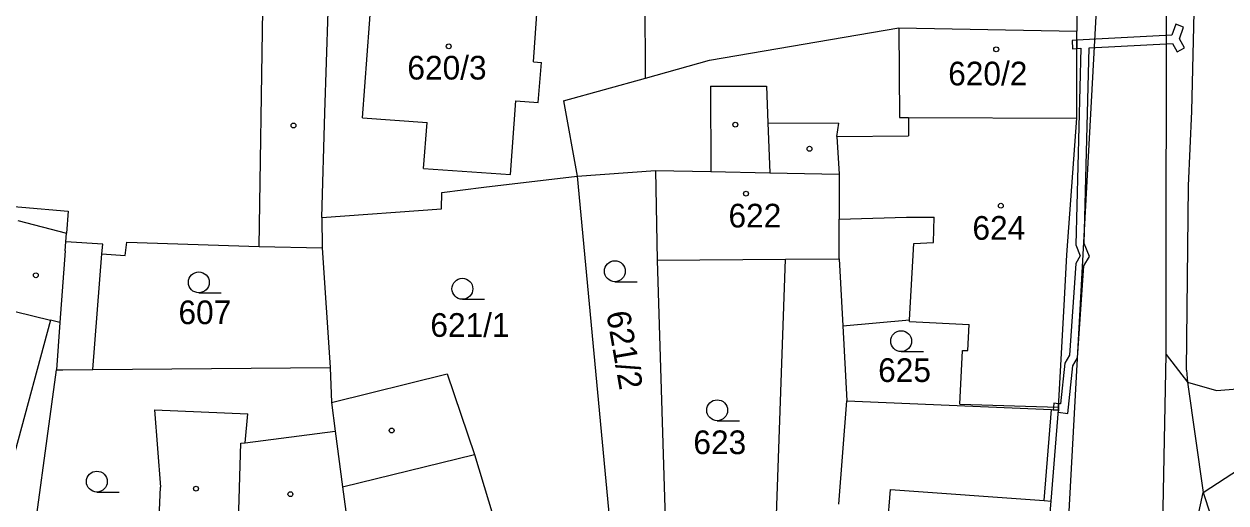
# Model space of a CAD drawing. Extents: x -785744 to -782822, y -1067550 to -1063910.
# Drawn here: x -783562.5 to -783476.2, y -1065679 to -1065644.6 of the extents above; entities that cross this region are included whole.
import ezdxf

# ---------------------------------------------------------------- set-up
doc = ezdxf.new("R2010")
doc.units = 0
for name, color, linetype in [('Hranice parcel', 7, 'Continuous'), ('Parcelní čísla', 7, 'Continuous'), ('Vnitřní kresba', 7, 'Continuous'), ('Věcná břemena k části', 7, 'Continuous'), ('Značky budov', 7, 'Continuous'), ('Značky kultur', 7, 'Continuous')]:
    doc.layers.add(name, color=color, linetype=linetype)

msp = doc.modelspace()

# ---------------------------------------------------------------- linework, layer by layer
at = {"layer": 'Hranice parcel'}
for p, q in [((-783517.88, -1065648.46), (-783517.92, -1065640.59)), ((-783517.88, -1065648.46), (-783513.29, -1065647.19)), ((-783523.78, -1065650.1), (-783517.88, -1065648.46)), ((-783559.36, -1065658.02), (-783559.47, -1065659.6)), ((-783562.96, -1065658.68), (-783559.47, -1065659.6)), ((-783560.63, -1065665.84), (-783563.19, -1065675.33)), ((-783559.94, -1065666.01), (-783560.63, -1065665.84))]:
    msp.add_line(p, q, dxfattribs=at)
for points in [[(-783486.9, -1065640.93), (-783486.91, -1065645.09)], [(-783478.66, -1065650.84), (-783478.44, -1065641.69)], [(-783538.22, -1065651.31), (-783537.54, -1065642.3)], [(-783540.91, -1065650.97), (-783540.69, -1065643.68)], [(-783525.94, -1065647.3), (-783525.64, -1065643.19)], [(-783513.29, -1065647.19), (-783499.7, -1065644.85)], [(-783499.7, -1065644.85), (-783486.91, -1065645.09)], [(-783486.92, -1065651.35), (-783486.91, -1065645.09)], [(-783525.94, -1065647.3), (-783525.37, -1065647.34)], [(-783525.59, -1065650.23), (-783525.37, -1065647.34)], [(-783527.59, -1065655.39), (-783527.19, -1065650.11)], [(-783527.19, -1065650.11), (-783525.59, -1065650.23)], [(-783523.78, -1065650.1), (-783522.79, -1065655.51)], [(-783541.14, -1065658.48), (-783540.91, -1065650.97)], [(-783538.22, -1065651.31), (-783533.58, -1065651.65)], [(-783533.83, -1065654.96), (-783533.58, -1065651.65)], [(-783499, -1065651.29), (-783486.92, -1065651.35)], [(-783499, -1065651.29), (-783498.99, -1065652.6)], [(-783487.62, -1065661.15), (-783486.92, -1065651.35)], [(-783478.89, -1065656.21), (-783478.66, -1065650.84)], [(-783504.15, -1065652.65), (-783498.99, -1065652.6)], [(-783504.15, -1065652.65), (-783503.99, -1065655.37)], [(-783533.83, -1065654.96), (-783527.59, -1065655.39)], [(-783522.79, -1065655.51), (-783517.17, -1065655.09)], [(-783517.17, -1065655.09), (-783517.06, -1065661.54)], [(-783517.17, -1065655.09), (-783513.19, -1065655.17)], [(-783529.51, -1065656.29), (-783522.79, -1065655.51)], [(-783522.79, -1065655.51), (-783520.15, -1065683.77)], [(-783513.19, -1065655.17), (-783508.95, -1065655.26)], [(-783508.95, -1065655.26), (-783503.99, -1065655.37)], [(-783503.99, -1065655.37), (-783503.98, -1065658.59)], [(-783532.55, -1065657.85), (-783532.52, -1065656.69)], [(-783532.52, -1065656.69), (-783529.51, -1065656.29)], [(-783479.03, -1065669.43), (-783478.89, -1065656.21)], [(-783566.02, -1065657.44), (-783559.36, -1065658.02)], [(-783541.14, -1065658.48), (-783532.55, -1065657.85)], [(-783541.14, -1065658.48), (-783541.1, -1065660.66)], [(-783503.98, -1065661.45), (-783503.98, -1065658.59)], [(-783559.56, -1065660.87), (-783559.51, -1065660.21)], [(-783559.51, -1065660.21), (-783559.47, -1065659.6)], [(-783555.25, -1065661.19), (-783555.14, -1065660.24)], [(-783555.14, -1065660.24), (-783545.64, -1065660.56)], [(-783559.56, -1065660.87), (-783559.94, -1065666.01)], [(-783557.59, -1065669.38), (-783556.93, -1065661.07)], [(-783556.93, -1065661.07), (-783555.25, -1065661.19)], [(-783545.64, -1065660.56), (-783541.1, -1065660.66)], [(-783541.1, -1065660.66), (-783540.54, -1065669.25)], [(-783487.82, -1065664.79), (-783487.62, -1065661.15)], [(-783517.06, -1065661.54), (-783507.83, -1065661.47)], [(-783517.06, -1065661.54), (-783516.43, -1065681.67)], [(-783508.51, -1065680.51), (-783507.83, -1065661.47)], [(-783503.98, -1065661.45), (-783503.72, -1065666.25)], [(-783488.23, -1065672.09), (-783487.82, -1065664.79)], [(-783559.94, -1065666.01), (-783560.19, -1065669.41)], [(-783503.72, -1065666.25), (-783498.94, -1065665.81)], [(-783503.72, -1065666.25), (-783503.43, -1065671.64)], [(-783498.94, -1065665.95), (-783498.94, -1065665.81)], [(-783498.94, -1065665.95), (-783494.64, -1065666.15)], [(-783494.73, -1065668.03), (-783494.64, -1065666.15)], [(-783495.32, -1065671.88), (-783495.13, -1065668.01)], [(-783495.13, -1065668.01), (-783494.73, -1065668.03)], [(-783476.88, -1065670.89), (-783441.51, -1065668.06)], [(-783562.28, -1065684.72), (-783560.19, -1065669.41)], [(-783560.19, -1065669.41), (-783559.74, -1065669.4)], [(-783559.74, -1065669.4), (-783557.59, -1065669.38)], [(-783557.59, -1065669.38), (-783540.54, -1065669.25)], [(-783540.54, -1065669.25), (-783540.44, -1065671.76)], [(-783540.44, -1065671.76), (-783532.13, -1065669.7)], [(-783532.13, -1065669.7), (-783530.18, -1065675.48)], [(-783479.03, -1065669.43), (-783478.96, -1065670.3)], [(-783478.96, -1065670.3), (-783477.83, -1065678.21)], [(-783478.96, -1065670.3), (-783476.88, -1065670.89)], [(-783553.15, -1065672.28), (-783552.72, -1065677.82)], [(-783553.15, -1065672.28), (-783546.46, -1065672.57)], [(-783540.44, -1065671.76), (-783540.18, -1065673.82)], [(-783504, -1065679.05), (-783503.43, -1065671.64)], [(-783503.43, -1065671.64), (-783488.73, -1065672.26)], [(-783495.32, -1065671.88), (-783488.23, -1065672.09)], [(-783488.76, -1065678.83), (-783488.24, -1065672.29)], [(-783488.73, -1065672.26), (-783488.24, -1065672.29)], [(-783488.24, -1065672.29), (-783488.23, -1065672.09)], [(-783546.64, -1065674.65), (-783546.46, -1065672.57)], [(-783546.64, -1065674.65), (-783540.18, -1065673.82)], [(-783540.18, -1065673.82), (-783539.65, -1065677.8)], [(-783530.18, -1065675.48), (-783528.46, -1065681.12)], [(-783552.92, -1065682.22), (-783552.72, -1065677.82)], [(-783539.65, -1065677.8), (-783538.64, -1065685.26)], [(-783477.83, -1065678.21), (-783476.79, -1065681.42)], [(-783489.53, -1065687.87), (-783488.76, -1065678.83)]]:
    msp.add_lwpolyline(points, dxfattribs=at)
at = {"layer": 'Vnitřní kresba'}
msp.add_line((-783564.63, -1065664.86), (-783560.63, -1065665.84), dxfattribs=at)
for points in [[(-783480.49, -1065668.31), (-783480.48, -1065638.77)], [(-783487.87, -1065687.01), (-783485.3, -1065640.06)], [(-783545.64, -1065660.56), (-783545.36, -1065643.57)], [(-783499.7, -1065644.85), (-783499.64, -1065651.29)], [(-783513.21, -1065649.04), (-783513.19, -1065655.17)], [(-783513.21, -1065649.04), (-783509.21, -1065649.05)], [(-783509.21, -1065649.05), (-783509.1, -1065651.69)], [(-783499.64, -1065651.29), (-783499, -1065651.29)], [(-783509.1, -1065651.69), (-783508.95, -1065655.26)], [(-783509.1, -1065651.69), (-783504, -1065651.71)], [(-783504.15, -1065652.65), (-783504, -1065651.71)], [(-783503.98, -1065658.59), (-783499.14, -1065658.45)], [(-783499.14, -1065658.45), (-783497.16, -1065658.44)], [(-783497.2, -1065660.26), (-783497.16, -1065658.44)], [(-783556.87, -1065660.38), (-783559.51, -1065660.21)], [(-783498.63, -1065660.34), (-783497.2, -1065660.26)], [(-783556.93, -1065661.07), (-783556.87, -1065660.38)], [(-783498.94, -1065665.81), (-783498.63, -1065660.34)], [(-783507.83, -1065661.47), (-783503.98, -1065661.45)], [(-783480.78, -1065683.02), (-783480.49, -1065668.31)], [(-783480.49, -1065668.31), (-783478.96, -1065670.3)], [(-783489.25, -1065678.79), (-783488.73, -1065672.26)], [(-783547.29, -1065685.92), (-783546.94, -1065674.68)], [(-783546.94, -1065674.68), (-783546.64, -1065674.65)], [(-783539.65, -1065677.8), (-783530.18, -1065675.48)], [(-783477.83, -1065678.21), (-783474.2, -1065675.85)], [(-783500.73, -1065683.36), (-783500.3, -1065678)], [(-783500.3, -1065678), (-783489.25, -1065678.79)], [(-783478.68, -1065682.09), (-783477.83, -1065678.21)], [(-783489.25, -1065678.79), (-783488.76, -1065678.83)]]:
    msp.add_lwpolyline(points, dxfattribs=at)
at = {"layer": 'Věcná břemena k části'}
for points in [[(-783479.81, -1065644.6), (-783480.08, -1065645.39)], [(-783479.25, -1065644.8), (-783479.81, -1065644.6)], [(-783480.08, -1065645.39), (-783486.91, -1065645.75)], [(-783479.53, -1065645.65), (-783479.25, -1065644.8)], [(-783486.91, -1065645.75), (-783487.25, -1065645.77)], [(-783487.25, -1065645.77), (-783487.22, -1065646.37)], [(-783487.22, -1065646.37), (-783486.91, -1065646.35)], [(-783486.62, -1065646.33), (-783486.98, -1065660.43)], [(-783486.91, -1065645.75), (-783486.91, -1065646.35)], [(-783486.91, -1065646.35), (-783486.91, -1065645.75)], [(-783486.91, -1065646.35), (-783486.62, -1065646.33)], [(-783486.38, -1065660.33), (-783486.02, -1065646.3)], [(-783486.02, -1065646.3), (-783480.03, -1065645.99)], [(-783480.03, -1065645.99), (-783479.7, -1065646.59)], [(-783479.7, -1065646.59), (-783479.18, -1065646.29)], [(-783479.18, -1065646.29), (-783479.53, -1065645.65)], [(-783486.98, -1065660.43), (-783486.67, -1065661.22)], [(-783486.01, -1065661.28), (-783486.38, -1065660.33)], [(-783486.99, -1065661.77), (-783487.44, -1065668.36)], [(-783486.67, -1065661.22), (-783486.99, -1065661.77)], [(-783486.86, -1065668.54), (-783486.41, -1065661.95)], [(-783486.41, -1065661.95), (-783486.01, -1065661.28)], [(-783487.77, -1065668.92), (-783488.09, -1065671.86)], [(-783487.44, -1065668.36), (-783487.77, -1065668.92)], [(-783487.19, -1065669.12), (-783486.86, -1065668.54)], [(-783487.55, -1065672.54), (-783487.19, -1065669.12)], [(-783488.59, -1065672.08), (-783488.61, -1065672.27)], [(-783488.61, -1065672.27), (-783488.24, -1065672.29)], [(-783488.56, -1065671.8), (-783488.59, -1065672.08)], [(-783488.22, -1065671.84), (-783488.56, -1065671.8)], [(-783488.24, -1065672.29), (-783488.25, -1065672.45)], [(-783488.23, -1065672.09), (-783488.24, -1065672.29)], [(-783488.24, -1065672.29), (-783488.23, -1065672.09)], [(-783488.22, -1065671.84), (-783488.23, -1065672.09)], [(-783488.23, -1065672.09), (-783488.22, -1065671.84)], [(-783488.09, -1065671.86), (-783488.22, -1065671.84)], [(-783488.25, -1065672.45), (-783487.55, -1065672.54)]]:
    msp.add_lwpolyline(points, dxfattribs=at)
at = {"layer": 'Značky budov'}
for centre in [(-783532.02, -1065646.19), (-783492.7, -1065646.4), (-783511.44, -1065651.81), (-783543.17, -1065651.87), (-783506.11, -1065653.54), (-783510.67, -1065656.76), (-783492.37, -1065657.63), (-783561.67, -1065662.62), (-783536.12, -1065673.76), (-783550.17, -1065677.94), (-783543.39, -1065678.33)]:
    msp.add_circle(centre, 0.175, dxfattribs=at)
at = {"layer": 'Značky kultur'}
for p, q in [((-783520.09, -1065663.08), (-783518.49, -1065663.08)), ((-783549.97, -1065663.88), (-783548.37, -1065663.88)), ((-783531.04, -1065664.34), (-783529.44, -1065664.34)), ((-783499.53, -1065668.1), (-783497.93, -1065668.1)), ((-783512.74, -1065673.06), (-783511.14, -1065673.06)), ((-783557.29, -1065678.18), (-783555.69, -1065678.18))]:
    msp.add_line(p, q, dxfattribs=at)
for centre in [(-783520.09, -1065662.33), (-783549.97, -1065663.13), (-783531.04, -1065663.59), (-783499.53, -1065667.35), (-783512.74, -1065672.31), (-783557.29, -1065677.43)]:
    msp.add_circle(centre, 0.75, dxfattribs=at)

# ---------------------------------------------------------------- texts
at = {"layer": 'Parcelní čísla'}
for s, p in [('620/3', (-783534.99, -1065648.57)), ('620/2', (-783496.15, -1065648.99)), ('622', (-783511.93, -1065659.19)), ('624', (-783494.41, -1065660.07)), ('607', (-783551.43, -1065666.13)), ('621/1', (-783533.34, -1065667.04)), ('625', (-783501.18, -1065670.28)), ('623', (-783514.45, -1065675.46))]:
    msp.add_text(s, height=1.7, dxfattribs=at).set_placement(p)
msp.add_text('621/2', height=1.7, rotation=279.85689, dxfattribs=at).set_placement((-783520.71, -1065665.32))

doc.saveas('drawing.dxf')
